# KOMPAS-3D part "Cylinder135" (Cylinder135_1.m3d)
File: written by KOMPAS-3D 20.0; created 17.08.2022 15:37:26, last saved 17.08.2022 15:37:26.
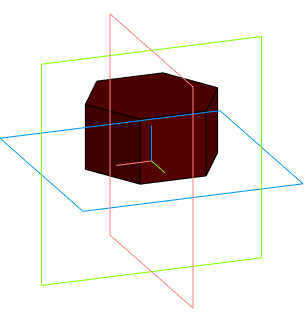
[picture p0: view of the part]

Document properties: Автор: artemsv220@gmail.com; Полное имя файла: \\192.168.2.25\новая общая папка\Медиа\Светильники\Кашпо\Кашпо и вазоны\DWG\Cylinder135_1.m3d

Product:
- Part/product: Cylinder135

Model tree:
1. Операция без истории:1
